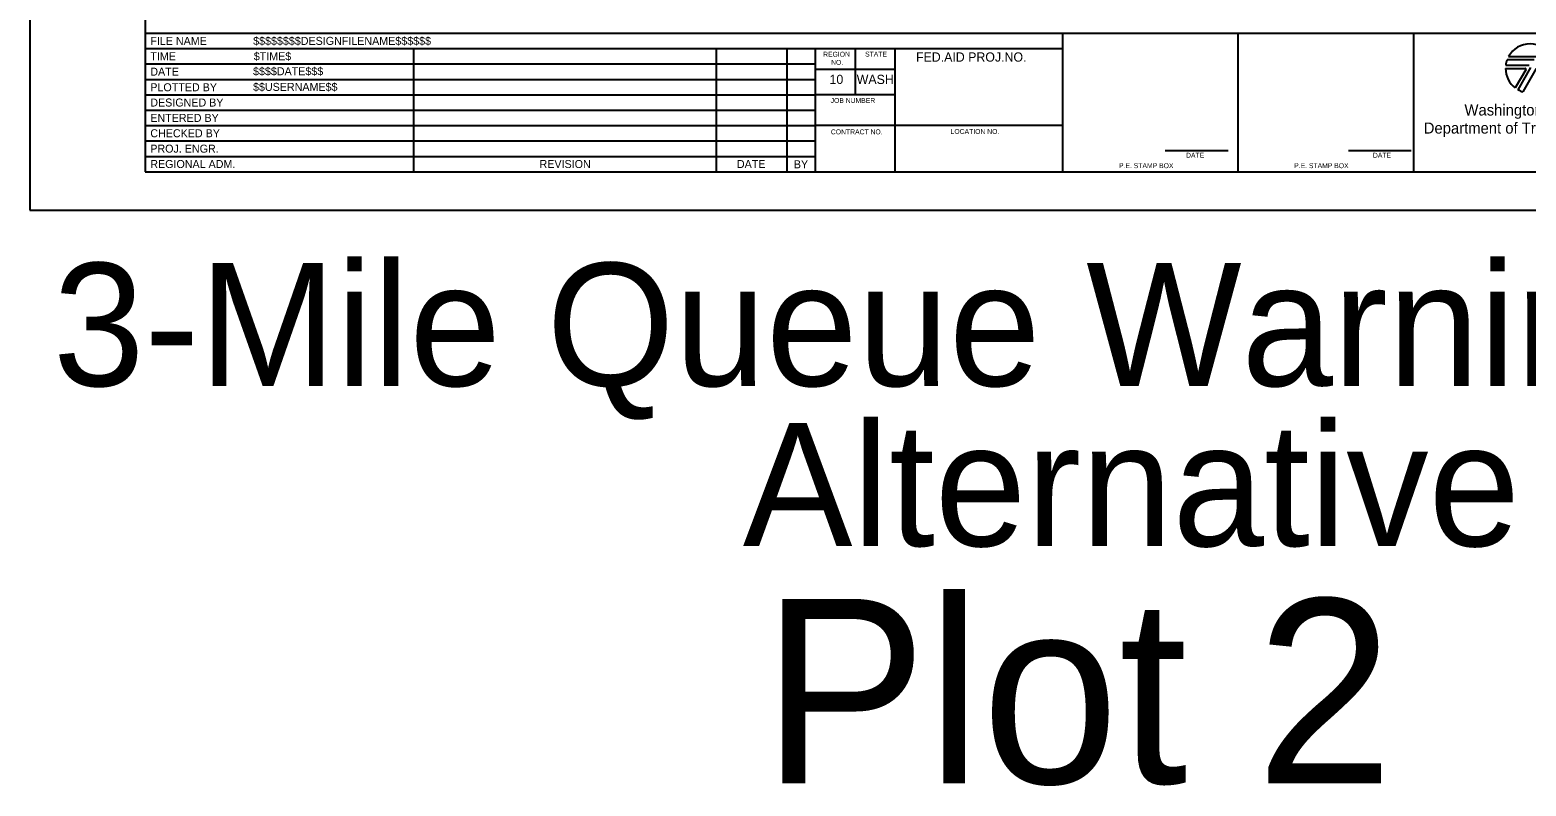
# Model space of a CAD drawing. Extents: x 99999 to 100116, y 99995 to 100013.
# Drawn here: x 100019.06 to 100031.22, y 99995.01 to 100001.15 of the extents above; entities that cross this region are included whole.
import ezdxf

# ---------------------------------------------------------------- set-up
doc = ezdxf.new("R2010")
doc.units = 0
for name, color, linetype in [('SH_GI_PlotLimits', 7, 'Continuous'), ('SH_GI_SheetBorder', 7, 'Continuous'), ('SH_GI_SheetLocationText', 7, 'Continuous'), ('SH_GI_SheetTextInCells', 7, 'Continuous'), ('SH_GI_TitleBlockText', 7, 'Continuous'), ('SH_GI_WSDOTLogo', 7, 'Continuous')]:
    doc.layers.add(name, color=color, linetype=linetype)

msp = doc.modelspace()

# ---------------------------------------------------------------- linework, layer by layer
at = {"layer": 'SH_GI_PlotLimits'}
msp.add_lwpolyline([(100019.062, 99999.687), (100036.062, 99999.687), (100036.062, 100010.687), (100019.062, 100010.687)], close=True, dxfattribs=at)
at = {"layer": 'SH_GI_SheetBorder'}
for p, q in [((100020, 100010.375), (100020, 100000)), ((100020, 100001.126), (100035.75, 100001.126)), ((100027.457, 100000), (100027.457, 100001.126)), ((100028.883, 100000), (100028.883, 100001.126)), ((100030.309, 100001.126), (100030.309, 100000)), ((100020, 100001.001), (100027.457, 100001.001)), ((100022.179, 100001.001), (100022.179, 100000)), ((100024.641, 100001.001), (100024.641, 100000)), ((100025.216, 100001.001), (100025.216, 100000)), ((100025.445, 100001.001), (100025.445, 100000)), ((100025.772, 100000.625), (100025.772, 100001.001)), ((100026.096, 100000), (100026.096, 100001.001)), ((100020, 100000.876), (100022.182, 100000.876)), ((100022.182, 100000.876), (100025.447, 100000.876)), ((100020, 100000.751), (100022.182, 100000.751)), ((100022.182, 100000.751), (100025.447, 100000.751)), ((100026.096, 100000.831), (100025.447, 100000.831)), ((100020, 100000.625), (100025.447, 100000.625)), ((100026.096, 100000.625), (100025.447, 100000.625)), ((100020, 100000.5), (100025.447, 100000.5)), ((100020, 100000.375), (100025.447, 100000.375)), ((100027.457, 100000.375), (100025.447, 100000.375)), ((100020, 100000.25), (100025.447, 100000.25)), ((100020, 100000.125), (100025.447, 100000.125)), ((100028.29, 100000.173), (100028.802, 100000.173)), ((100029.78, 100000.173), (100030.291, 100000.173)), ((100020, 100000), (100035.75, 100000))]:
    msp.add_line(p, q, dxfattribs=at)
at = {"layer": 'SH_GI_WSDOTLogo'}
for p, q in [((100031.057, 100000.84), (100031.215, 100000.84)), ((100031.059, 100000.866), (100031.25, 100000.866)), ((100031.289, 100000.909), (100031.07, 100000.909)), ((100031.303, 100000.935), (100031.081, 100000.935)), ((100031.261, 100000.846), (100031.157, 100000.667)), ((100031.199, 100000.649), (100031.309, 100000.839)), ((100031.222, 100000.828), (100031.136, 100000.681))]:
    msp.add_line(p, q, dxfattribs=at)
for centre, radius, start, end in [((100031.257, 100000.84), 0.2, 28.4787, 151.532), ((100031.257, 100000.84), 0.2, 179.9986, 232.8433), ((100031.257, 100000.84), 0.2, 159.696, 172.5057), ((100031.215, 100000.832), 0.0082, 329.7436, 90), ((100031.257, 100000.84), 0.2, 239.7929, 253.0448)]:
    msp.add_arc(centre, radius, start, end, dxfattribs=at)

# ---------------------------------------------------------------- texts
at = {"layer": 'SH_GI_SheetLocationText'}
for s, height, p in [('3-Mile Queue Warning System', 1, (100019.25, 99998.258)), ('Alternative', 1, (100024.857, 99996.956)), ('Plot 2', 1.5, (100025.015, 99995.027))]:
    msp.add_text(s, height=height, dxfattribs=at).set_placement(p)
at = {"layer": 'SH_GI_SheetTextInCells'}
for s, height, p in [('FILE NAME', 0.0651, (100020.041, 100001.031)), ('TIME', 0.0651, (100020.041, 100000.906)), ('REGION', 0.04, (100025.51, 100000.935)), ('STATE', 0.04, (100025.851, 100000.936)), ('FED.AID PROJ.NO.', 0.07506, (100026.265, 100000.895)), ('DATE', 0.0651, (100020.041, 100000.781)), ('NO.', 0.04, (100025.575, 100000.869)), ('PLOTTED BY', 0.0651, (100020.041, 100000.654)), ('10', 0.0751, (100025.562, 100000.713)), ('WASH', 0.0751, (100025.783, 100000.713)), ('DESIGNED BY', 0.06505, (100020.041, 100000.53)), ('JOB NUMBER', 0.04, (100025.571, 100000.559)), ('Washington State', 0.09007, (100030.723, 100000.457)), ('ENTERED BY', 0.0651, (100020.041, 100000.405)), ('Department of Transportation', 0.09007, (100030.392, 100000.31)), ('CHECKED BY', 0.0651, (100020.041, 100000.28)), ('CONTRACT NO.', 0.04003, (100025.573, 100000.304)), ('LOCATION NO.', 0.04003, (100026.546, 100000.307)), ('PROJ. ENGR.', 0.06505, (100020.041, 100000.155)), ('DATE', 0.04, (100028.46, 100000.114)), ('DATE', 0.04, (100029.979, 100000.114)), ('REGIONAL ADM.', 0.06505, (100020.041, 100000.03)), ('REVISION', 0.0651, (100023.205, 100000.03)), ('DATE', 0.0651, (100024.809, 100000.03)), ('BY', 0.0651, (100025.272, 100000.028)), ('P.E. STAMP BOX', 0.04003, (100027.915, 100000.029)), ('P.E. STAMP BOX', 0.04003, (100029.339, 100000.029))]:
    msp.add_text(s, height=height, dxfattribs=at).set_placement(p)
at = {"layer": 'SH_GI_TitleBlockText'}
for s, height, p in [('$$$$$$$$DESIGNFILENAME$$$$$$', 0.06505, (100020.877, 100001.031)), ('$TIME$', 0.0651, (100020.882, 100000.906)), ('$$$$DATE$$$', 0.06505, (100020.876, 100000.784)), ('$$USERNAME$$', 0.06505, (100020.876, 100000.657))]:
    msp.add_text(s, height=height, dxfattribs=at).set_placement(p)

doc.saveas('drawing.dxf')
